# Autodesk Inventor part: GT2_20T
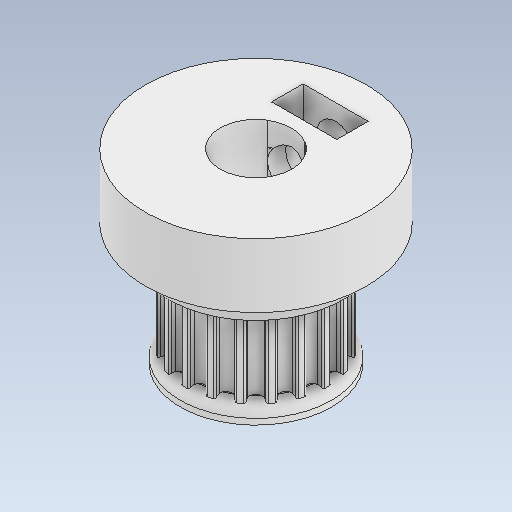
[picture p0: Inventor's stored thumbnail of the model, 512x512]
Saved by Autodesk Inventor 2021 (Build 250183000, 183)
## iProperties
Created: 2023-10
Part Number: GT2_20T
Material: Plastica ABS
Document SubType Name: Modeling
Designer: hp
Density: 1.06 g/cm^3
Appearance: Default
Author: hp
Revision Number: ANY
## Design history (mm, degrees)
feature "Solido1"
body "Solid1"
